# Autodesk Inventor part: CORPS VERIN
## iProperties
Created: 2004-11
Part Number: CORPS VERIN
Document SubType Name: Modeling
Designer: Bruno
Manufacturer: Standard
Standards Organization: Custom
Author: Bruno
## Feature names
1. Base1
2. Extrusion1
